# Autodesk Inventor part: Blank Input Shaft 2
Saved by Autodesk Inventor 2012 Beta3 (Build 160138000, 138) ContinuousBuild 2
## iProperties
Created: 2011-01
Part Number: Blank Input Shaft 2
Material: Steel
Document SubType Name: Modeling
Designer: Beta-8540w
Density: 1 g/cm^3
CustomPartVersion: 1
Author: Beta-8540w
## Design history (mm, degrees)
sketch "Main Sketch"
  geometry: L1 (0, 0)-(43, 0) reference; L2 (0, 0)-(0, 45); L3 (12, 45)-(12, 6); L4 (0, 45)-(12, 45); L5 (15, 6)-(15, 5); L6 (12, 6)-(15, 6); L7 (43, 5)-(43, 0); L8 (15, 5)-(43, 5)
  constraints: 16 end point, 5 horizontal, 4 vertical
  dimensions: "d3" = 90 diameter of L4 L1 (derived); "d4" = 12 diameter of L6 L1 (derived); "d5" = 10 diameter of L8 L1 (derived)
revolve "Revolution1" sketch "Main Sketch" stored, may be unused: angle "d6" = 0 deg
chamfer "Chamfer1" distance "d7" = 0.5; stored, may be unused: second distance "d8" = 0.125, angle "d9" = 45 deg
node "Retaining Ring Groove1"
body "Solid1"
feature "iFeature27:1"
other parameters: "d0" = 0, "d1" = 0, "d2" = 0
